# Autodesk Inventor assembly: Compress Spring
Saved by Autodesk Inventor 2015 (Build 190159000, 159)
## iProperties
Created: 2014-07
Part Number: Compress Spring
Document SubType Name: Assembly
Designer: User
ClientObjectVersion: 1
Author: User
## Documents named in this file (2)
- Z:\CAD Files\Belt_Extruder\Rev. C\Extruder_Assembly_Rev_3\Design Accelerator\Compress Spring1.iam
- Z:\CAD Files\Belt_Extruder\Rev. C\Extruder_Assembly_Rev_3\Design Accelerator\Compress Spring11.ipt
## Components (1 placed, 1 different names)
1. Compress Spring1:1
